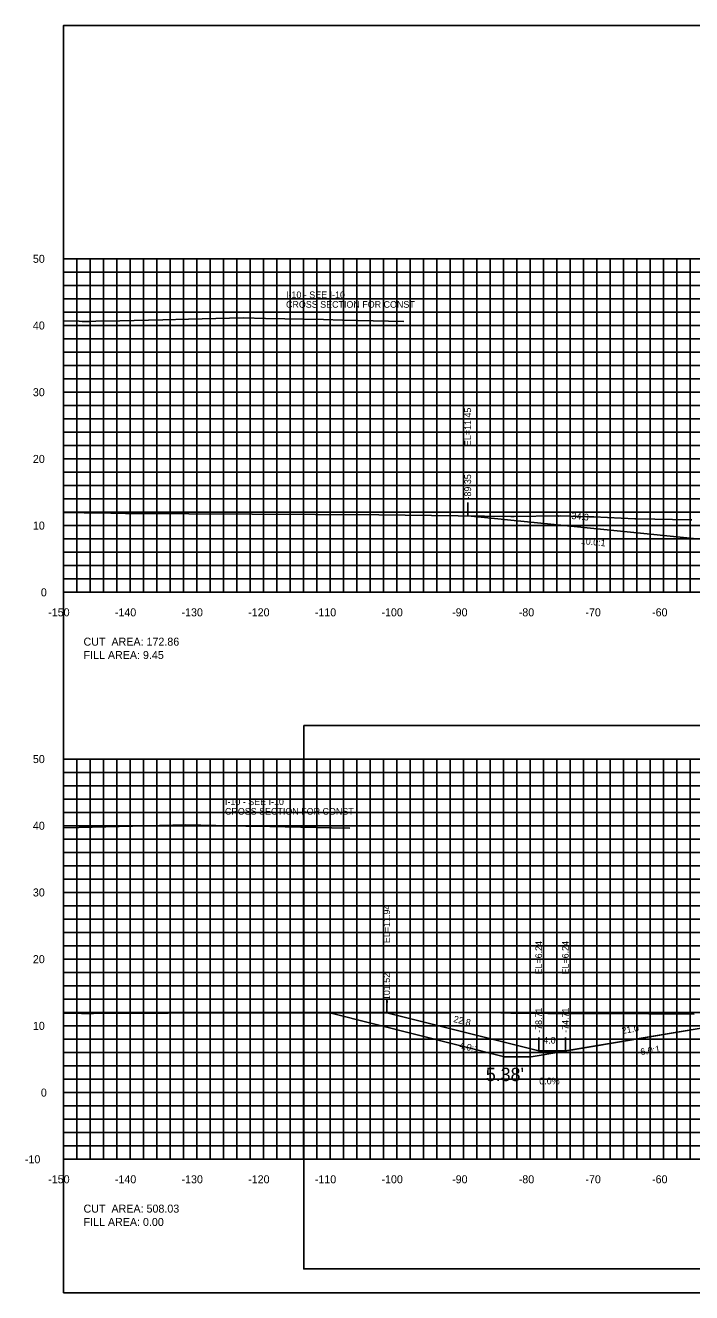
# Model space of a CAD drawing. Extents: x 1797305 to 1804485, y 245831 to 250849.
# Drawn here: x 1802135.3 to 1802235.2, y 250079.4 to 250269.4 of the extents above; entities that cross this region are included whole.
import ezdxf

# ---------------------------------------------------------------- set-up
doc = ezdxf.new("R2010")
doc.units = 0
for name, color, linetype in [('1', 7, 'Continuous'), ('10', 7, 'Continuous'), ('29', 7, 'Continuous'), ('60', 7, 'Continuous'), ('BASE', 7, 'Continuous'), ('CL-CNST', 7, 'Continuous'), ('EDPV-LINE', 7, 'Continuous'), ('Level 31', 7, 'Continuous'), ('LIMT-CSLINE', 7, 'Continuous'), ('M-ROADS', 7, 'Continuous')]:
    doc.layers.add(name, color=color, linetype=linetype)

msp = doc.modelspace()

# ---------------------------------------------------------------- linework, layer by layer
for p, q in [((1802201.65, 250195.88), (1802201.65, 250197.88)), ((1802189.49, 250121.37), (1802189.49, 250123.37)), ((1802212.29, 250115.67), (1802212.29, 250117.67)), ((1802216.29, 250115.67), (1802216.29, 250117.67))]:
    msp.add_line(p, q)
msp.add_lwpolyline([(1802141, 250079.43), (1802441, 250079.43), (1802441, 250269.43), (1802141, 250269.43)], close=True)
at = {"layer": '1'}
for p, q in [((1802207.14, 250114.81), (1802180.97, 250121.36)), ((1802237.29, 250119.17), (1802211.14, 250114.81)), ((1802211.14, 250114.81), (1802207.14, 250114.81))]:
    msp.add_line(p, q, dxfattribs=at)
msp.add_lwpolyline([(1802177.03, 250164.46), (1802249.79, 250164.46), (1802249.79, 250082.99), (1802177.03, 250082.99)], close=True, dxfattribs=at)
at = {"layer": '29'}
for p, q in [((1802141, 250234.43), (1802441, 250234.43)), ((1802141, 250184.43), (1802141, 250234.43)), ((1802143, 250184.43), (1802143, 250234.43)), ((1802145, 250184.43), (1802145, 250234.43)), ((1802147, 250184.43), (1802147, 250234.43)), ((1802149, 250184.43), (1802149, 250234.43)), ((1802151, 250184.43), (1802151, 250234.43)), ((1802153, 250184.43), (1802153, 250234.43)), ((1802155, 250184.43), (1802155, 250234.43)), ((1802157, 250184.43), (1802157, 250234.43)), ((1802159, 250184.43), (1802159, 250234.43)), ((1802161, 250184.43), (1802161, 250234.43)), ((1802163, 250184.43), (1802163, 250234.43)), ((1802165, 250184.43), (1802165, 250234.43)), ((1802167, 250184.43), (1802167, 250234.43)), ((1802169, 250184.43), (1802169, 250234.43)), ((1802171, 250184.43), (1802171, 250234.43)), ((1802173, 250184.43), (1802173, 250234.43)), ((1802175, 250184.43), (1802175, 250234.43)), ((1802177, 250184.43), (1802177, 250234.43)), ((1802179, 250184.43), (1802179, 250234.43)), ((1802181, 250184.43), (1802181, 250234.43)), ((1802183, 250184.43), (1802183, 250234.43)), ((1802185, 250184.43), (1802185, 250234.43)), ((1802187, 250184.43), (1802187, 250234.43)), ((1802189, 250184.43), (1802189, 250234.43)), ((1802191, 250184.43), (1802191, 250234.43)), ((1802193, 250184.43), (1802193, 250234.43)), ((1802195, 250184.43), (1802195, 250234.43)), ((1802197, 250184.43), (1802197, 250234.43)), ((1802199, 250184.43), (1802199, 250234.43)), ((1802201, 250184.43), (1802201, 250234.43)), ((1802203, 250184.43), (1802203, 250234.43)), ((1802205, 250184.43), (1802205, 250234.43)), ((1802207, 250184.43), (1802207, 250234.43)), ((1802209, 250184.43), (1802209, 250234.43)), ((1802211, 250184.43), (1802211, 250234.43)), ((1802213, 250184.43), (1802213, 250234.43)), ((1802215, 250184.43), (1802215, 250234.43)), ((1802217, 250184.43), (1802217, 250234.43)), ((1802219, 250184.43), (1802219, 250234.43)), ((1802221, 250184.43), (1802221, 250234.43)), ((1802223, 250184.43), (1802223, 250234.43)), ((1802225, 250184.43), (1802225, 250234.43)), ((1802227, 250184.43), (1802227, 250234.43)), ((1802229, 250184.43), (1802229, 250234.43)), ((1802231, 250184.43), (1802231, 250234.43)), ((1802233, 250184.43), (1802233, 250234.43)), ((1802235, 250184.43), (1802235, 250234.43)), ((1802141, 250232.43), (1802441, 250232.43)), ((1802141, 250230.43), (1802441, 250230.43)), ((1802141, 250228.43), (1802441, 250228.43)), ((1802141, 250226.43), (1802441, 250226.43)), ((1802141, 250224.43), (1802441, 250224.43)), ((1802141, 250222.43), (1802441, 250222.43)), ((1802141, 250220.43), (1802441, 250220.43)), ((1802141, 250218.43), (1802441, 250218.43)), ((1802141, 250216.43), (1802441, 250216.43)), ((1802141, 250214.43), (1802441, 250214.43)), ((1802141, 250212.43), (1802441, 250212.43)), ((1802141, 250210.43), (1802441, 250210.43)), ((1802141, 250208.43), (1802441, 250208.43)), ((1802141, 250206.43), (1802441, 250206.43)), ((1802141, 250204.43), (1802441, 250204.43)), ((1802141, 250202.43), (1802441, 250202.43)), ((1802141, 250200.43), (1802441, 250200.43)), ((1802141, 250198.43), (1802441, 250198.43)), ((1802141, 250196.43), (1802441, 250196.43)), ((1802141, 250194.43), (1802441, 250194.43)), ((1802141, 250192.43), (1802441, 250192.43)), ((1802141, 250190.43), (1802441, 250190.43)), ((1802141, 250188.43), (1802441, 250188.43)), ((1802141, 250186.43), (1802441, 250186.43)), ((1802141, 250184.43), (1802441, 250184.43)), ((1802141, 250159.43), (1802441, 250159.43)), ((1802141, 250099.43), (1802141, 250159.43)), ((1802143, 250099.43), (1802143, 250159.43)), ((1802145, 250099.43), (1802145, 250159.43)), ((1802147, 250099.43), (1802147, 250159.43)), ((1802149, 250099.43), (1802149, 250159.43)), ((1802151, 250099.43), (1802151, 250159.43)), ((1802153, 250099.43), (1802153, 250159.43)), ((1802155, 250099.43), (1802155, 250159.43)), ((1802157, 250099.43), (1802157, 250159.43)), ((1802159, 250099.43), (1802159, 250159.43)), ((1802161, 250099.43), (1802161, 250159.43)), ((1802163, 250099.43), (1802163, 250159.43)), ((1802165, 250099.43), (1802165, 250159.43)), ((1802167, 250099.43), (1802167, 250159.43)), ((1802169, 250099.43), (1802169, 250159.43)), ((1802171, 250099.43), (1802171, 250159.43)), ((1802173, 250099.43), (1802173, 250159.43)), ((1802175, 250099.43), (1802175, 250159.43)), ((1802177, 250099.43), (1802177, 250159.43)), ((1802179, 250099.43), (1802179, 250159.43)), ((1802181, 250099.43), (1802181, 250159.43)), ((1802183, 250099.43), (1802183, 250159.43)), ((1802185, 250099.43), (1802185, 250159.43)), ((1802187, 250099.43), (1802187, 250159.43)), ((1802189, 250099.43), (1802189, 250159.43)), ((1802191, 250099.43), (1802191, 250159.43)), ((1802193, 250099.43), (1802193, 250159.43)), ((1802195, 250099.43), (1802195, 250159.43)), ((1802197, 250099.43), (1802197, 250159.43)), ((1802199, 250099.43), (1802199, 250159.43)), ((1802201, 250099.43), (1802201, 250159.43)), ((1802203, 250099.43), (1802203, 250159.43)), ((1802205, 250099.43), (1802205, 250159.43)), ((1802207, 250099.43), (1802207, 250159.43)), ((1802209, 250099.43), (1802209, 250159.43)), ((1802211, 250099.43), (1802211, 250159.43)), ((1802213, 250099.43), (1802213, 250159.43)), ((1802215, 250099.43), (1802215, 250159.43)), ((1802217, 250099.43), (1802217, 250159.43)), ((1802219, 250099.43), (1802219, 250159.43)), ((1802221, 250099.43), (1802221, 250159.43)), ((1802223, 250099.43), (1802223, 250159.43)), ((1802225, 250099.43), (1802225, 250159.43)), ((1802227, 250099.43), (1802227, 250159.43)), ((1802229, 250099.43), (1802229, 250159.43)), ((1802231, 250099.43), (1802231, 250159.43)), ((1802233, 250099.43), (1802233, 250159.43)), ((1802235, 250099.43), (1802235, 250159.43)), ((1802141, 250157.43), (1802441, 250157.43)), ((1802141, 250155.43), (1802441, 250155.43)), ((1802141, 250153.43), (1802441, 250153.43)), ((1802141, 250151.43), (1802441, 250151.43)), ((1802141, 250149.43), (1802441, 250149.43)), ((1802141, 250147.43), (1802441, 250147.43)), ((1802141, 250145.43), (1802441, 250145.43)), ((1802141, 250143.43), (1802441, 250143.43)), ((1802141, 250141.43), (1802441, 250141.43)), ((1802141, 250139.43), (1802441, 250139.43)), ((1802141, 250137.43), (1802441, 250137.43)), ((1802141, 250135.43), (1802441, 250135.43)), ((1802141, 250133.43), (1802441, 250133.43)), ((1802141, 250131.43), (1802441, 250131.43)), ((1802141, 250129.43), (1802441, 250129.43)), ((1802141, 250127.43), (1802441, 250127.43)), ((1802141, 250125.43), (1802441, 250125.43)), ((1802141, 250123.43), (1802441, 250123.43)), ((1802141, 250121.43), (1802441, 250121.43)), ((1802141, 250119.43), (1802441, 250119.43)), ((1802141, 250117.43), (1802441, 250117.43)), ((1802141, 250115.43), (1802441, 250115.43)), ((1802141, 250113.43), (1802441, 250113.43)), ((1802141, 250111.43), (1802441, 250111.43)), ((1802141, 250109.43), (1802441, 250109.43)), ((1802141, 250107.43), (1802441, 250107.43)), ((1802141, 250105.43), (1802441, 250105.43)), ((1802141, 250103.43), (1802441, 250103.43)), ((1802141, 250101.43), (1802441, 250101.43)), ((1802141, 250099.43), (1802441, 250099.43))]:
    msp.add_line(p, q, dxfattribs=at)
at = {"layer": 'CL-CNST'}
for points in [[(1802141, 250225.11), (1802143.34, 250225.06), (1802143.81, 250225.05), (1802144.59, 250225.04), (1802144.59, 250225.04), (1802144.59, 250225.04), (1802145.06, 250225.05), (1802145.85, 250225.06), (1802149.45, 250225.15), (1802155.89, 250225.29), (1802159.76, 250225.38), (1802167.94, 250225.56), (1802171.3, 250225.49), (1802179.99, 250225.31), (1802182.84, 250225.25), (1802192.04, 250225.05)], [(1802201.65, 250195.88), (1802236, 250192.45), (1802240, 250192.45), (1802261, 250195.95), (1802263, 250196.03), (1802267, 250196.19), (1802291, 250195.66), (1802299, 250195.34), (1802301, 250195.26), (1802322, 250191.76), (1802326, 250191.76), (1802343.07, 250196.03)], [(1802141, 250149.14), (1802143.28, 250149.19), (1802147.34, 250149.29), (1802155.42, 250149.47), (1802159.37, 250149.57), (1802168.37, 250149.38), (1802171.97, 250149.3), (1802181.2, 250149.11), (1802183.98, 250149.05)], [(1802189.49, 250121.37), (1802212.29, 250115.67), (1802216.29, 250115.67), (1802237.29, 250119.17), (1802242.79, 250119.39), (1802246.79, 250119.55), (1802270.76, 250119.02), (1802291, 250118.58), (1802338.6, 250117.53), (1802338.61, 250117.38), (1802338.61, 250116.81)]]:
    msp.add_lwpolyline(points, dxfattribs=at)
at = {"layer": 'Level 31'}
for p, q in [((1802140.94, 250234.43), (1802141, 250234.43)), ((1802141, 250184.43), (1802141, 250234.43)), ((1802140.94, 250224.43), (1802141, 250224.43)), ((1802140.94, 250214.43), (1802141, 250214.43)), ((1802140.94, 250204.43), (1802141, 250204.43)), ((1802140.94, 250194.43), (1802141, 250194.43)), ((1802140.94, 250184.43), (1802141, 250184.43)), ((1802141, 250184.43), (1802441, 250184.43)), ((1802141, 250184.37), (1802141, 250184.43)), ((1802151, 250184.37), (1802151, 250184.43)), ((1802161, 250184.37), (1802161, 250184.43)), ((1802171, 250184.37), (1802171, 250184.43)), ((1802181, 250184.37), (1802181, 250184.43)), ((1802191, 250184.37), (1802191, 250184.43)), ((1802201, 250184.37), (1802201, 250184.43)), ((1802211, 250184.37), (1802211, 250184.43)), ((1802221, 250184.37), (1802221, 250184.43)), ((1802231, 250184.37), (1802231, 250184.43)), ((1802140.94, 250159.43), (1802141, 250159.43)), ((1802141, 250099.43), (1802141, 250159.43)), ((1802140.94, 250149.43), (1802141, 250149.43)), ((1802140.94, 250139.43), (1802141, 250139.43)), ((1802140.94, 250129.43), (1802141, 250129.43)), ((1802140.94, 250119.43), (1802141, 250119.43)), ((1802140.94, 250109.43), (1802141, 250109.43)), ((1802140.94, 250099.43), (1802141, 250099.43)), ((1802141, 250099.43), (1802441, 250099.43)), ((1802141, 250099.37), (1802141, 250099.43)), ((1802151, 250099.37), (1802151, 250099.43)), ((1802161, 250099.37), (1802161, 250099.43)), ((1802171, 250099.37), (1802171, 250099.43)), ((1802181, 250099.37), (1802181, 250099.43)), ((1802191, 250099.37), (1802191, 250099.43)), ((1802201, 250099.37), (1802201, 250099.43)), ((1802211, 250099.37), (1802211, 250099.43)), ((1802221, 250099.37), (1802221, 250099.43)), ((1802231, 250099.37), (1802231, 250099.43))]:
    msp.add_line(p, q, dxfattribs=at)
at = {"layer": 'M-ROADS'}
for points in [[(1802141, 250196.39), (1802144.1, 250196.36), (1802144.54, 250196.35), (1802145.4, 250196.35), (1802145.87, 250196.35), (1802145.9, 250196.35), (1802150.3, 250196.27), (1802188.32, 250196.03), (1802208.09, 250195.81), (1802208.32, 250195.81), (1802208.59, 250195.81), (1802215.14, 250195.88), (1802215.25, 250195.87), (1802215.63, 250195.88), (1802219.77, 250195.77), (1802219.98, 250195.76), (1802220.58, 250195.74), (1802226.71, 250195.47), (1802227.08, 250195.47), (1802235.04, 250195.3), (1802235.27, 250195.3)], [(1802141, 250121.34), (1802141.41, 250121.34), (1802141.51, 250121.34), (1802141.54, 250121.34), (1802143.68, 250121.29), (1802145.51, 250121.26), (1802156.71, 250121.31), (1802198.45, 250121.39), (1802199.13, 250121.36), (1802201.32, 250121.41), (1802202.11, 250121.43), (1802205.1, 250121.41), (1802208.13, 250121.35), (1802210.84, 250121.31), (1802216.48, 250121.24), (1802218.53, 250121.26), (1802221.17, 250121.27), (1802224.23, 250121.26), (1802224.4, 250121.26), (1802228.83, 250121.22), (1802235.64, 250121.18)]]:
    msp.add_lwpolyline(points, dxfattribs=at)

# ---------------------------------------------------------------- texts
for s, rotation, p in [('10.0:1', 354.2894, (1802218.58, 250191.68)), ('4.0:1', 345.9638, (1802200.28, 250116.1)), ('-6.0:1', 9.4623, (1802227.2, 250114.95))]:
    msp.add_text(s, height=1, rotation=rotation).set_placement(p)
at = {"layer": '1'}
msp.add_text("5.38'", height=2, dxfattribs=at).set_placement((1802204.36, 250111.15))
at = {"layer": '10'}
for s, p in [('-150', (1802138.7, 250180.83)), ('-140', (1802148.7, 250180.83)), ('-130', (1802158.7, 250180.83)), ('-120', (1802168.7, 250180.83)), ('-110', (1802178.7, 250180.83)), ('-100', (1802188.7, 250180.83)), ('-90', (1802199.3, 250180.83)), ('-80', (1802209.3, 250180.83)), ('-70', (1802219.3, 250180.83)), ('-60', (1802229.3, 250180.83)), ('-150', (1802138.7, 250095.83)), ('-140', (1802148.7, 250095.83)), ('-130', (1802158.7, 250095.83)), ('-120', (1802168.7, 250095.83)), ('-110', (1802178.7, 250095.83)), ('-100', (1802188.7, 250095.83)), ('-90', (1802199.3, 250095.83)), ('-80', (1802209.3, 250095.83)), ('-70', (1802219.3, 250095.83)), ('-60', (1802229.3, 250095.83))]:
    msp.add_text(s, height=1.2, dxfattribs=at).set_placement(p)
at = {"layer": '60'}
for s, p in [('50', (1802136.4, 250233.83)), ('40', (1802136.4, 250223.83)), ('30', (1802136.4, 250213.83)), ('20', (1802136.4, 250203.83)), ('10', (1802136.4, 250193.83)), ('0', (1802137.6, 250183.83)), ('50', (1802136.4, 250158.83)), ('40', (1802136.4, 250148.83)), ('30', (1802136.4, 250138.83)), ('20', (1802136.4, 250128.83)), ('10', (1802136.4, 250118.83)), ('0', (1802137.6, 250108.83)), ('-10', (1802135.2, 250098.83))]:
    msp.add_text(s, height=1.2, dxfattribs=at).set_placement(p)
at = {"layer": 'BASE'}
for s, rotation, p in [('34.3', 354.2894, (1802217.17, 250195.43)), ('22.8', 345.9638, (1802199.43, 250120.02)), ('21.0', 9.4623, (1802224.82, 250118.21))]:
    msp.add_text(s, height=1, rotation=rotation, dxfattribs=at).set_placement(p)
for s, p in [('4.0', (1802212.97, 250116.77)), ('0.0%', (1802212.38, 250110.67))]:
    msp.add_text(s, height=1, dxfattribs=at).set_placement(p)
at = {"layer": 'EDPV-LINE'}
for s, p in [('CUT  AREA: 172.86', (1802144, 250176.43)), ('FILL AREA: 9.45', (1802144, 250174.43)), ('CUT  AREA: 508.03', (1802144, 250091.43)), ('FILL AREA: 0.00', (1802144, 250089.43))]:
    msp.add_text(s, height=1.2, dxfattribs=at).set_placement(p)
at = {"layer": 'Level 31'}
for p in [(1802141, 250184.43), (1802141, 250099.43)]:
    msp.add_text('-', height=0.0001, dxfattribs=at).set_placement(p)
at = {"layer": 'LIMT-CSLINE'}
for s, p in [('CROSS SECTION FOR CONST ', (1802174.38, 250227.09)), ('I-10 - SEE I-10', (1802174.38, 250228.53)), ('CROSS SECTION FOR CONST ', (1802165.22, 250151.09)), ('I-10 - SEE I-10', (1802165.22, 250152.53))]:
    msp.add_text(s, height=1, dxfattribs=at).set_placement(p)
for s, p in [('EL=11.45', (1802202.15, 250206.35)), ('-89.35', (1802202.15, 250198.34)), ('EL=11.94', (1802189.99, 250131.84)), ('EL=6.24', (1802212.79, 250127.13)), ('EL=6.24', (1802216.79, 250127.13)), ('-101.52', (1802189.99, 250122.84)), ('-78.71', (1802212.79, 250118.38)), ('-74.71', (1802216.79, 250118.38))]:
    msp.add_text(s, height=1, rotation=90, dxfattribs=at).set_placement(p)

doc.saveas('drawing.dxf')
